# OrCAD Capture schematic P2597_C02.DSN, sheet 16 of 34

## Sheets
16 18_CSI Connector: size Custom
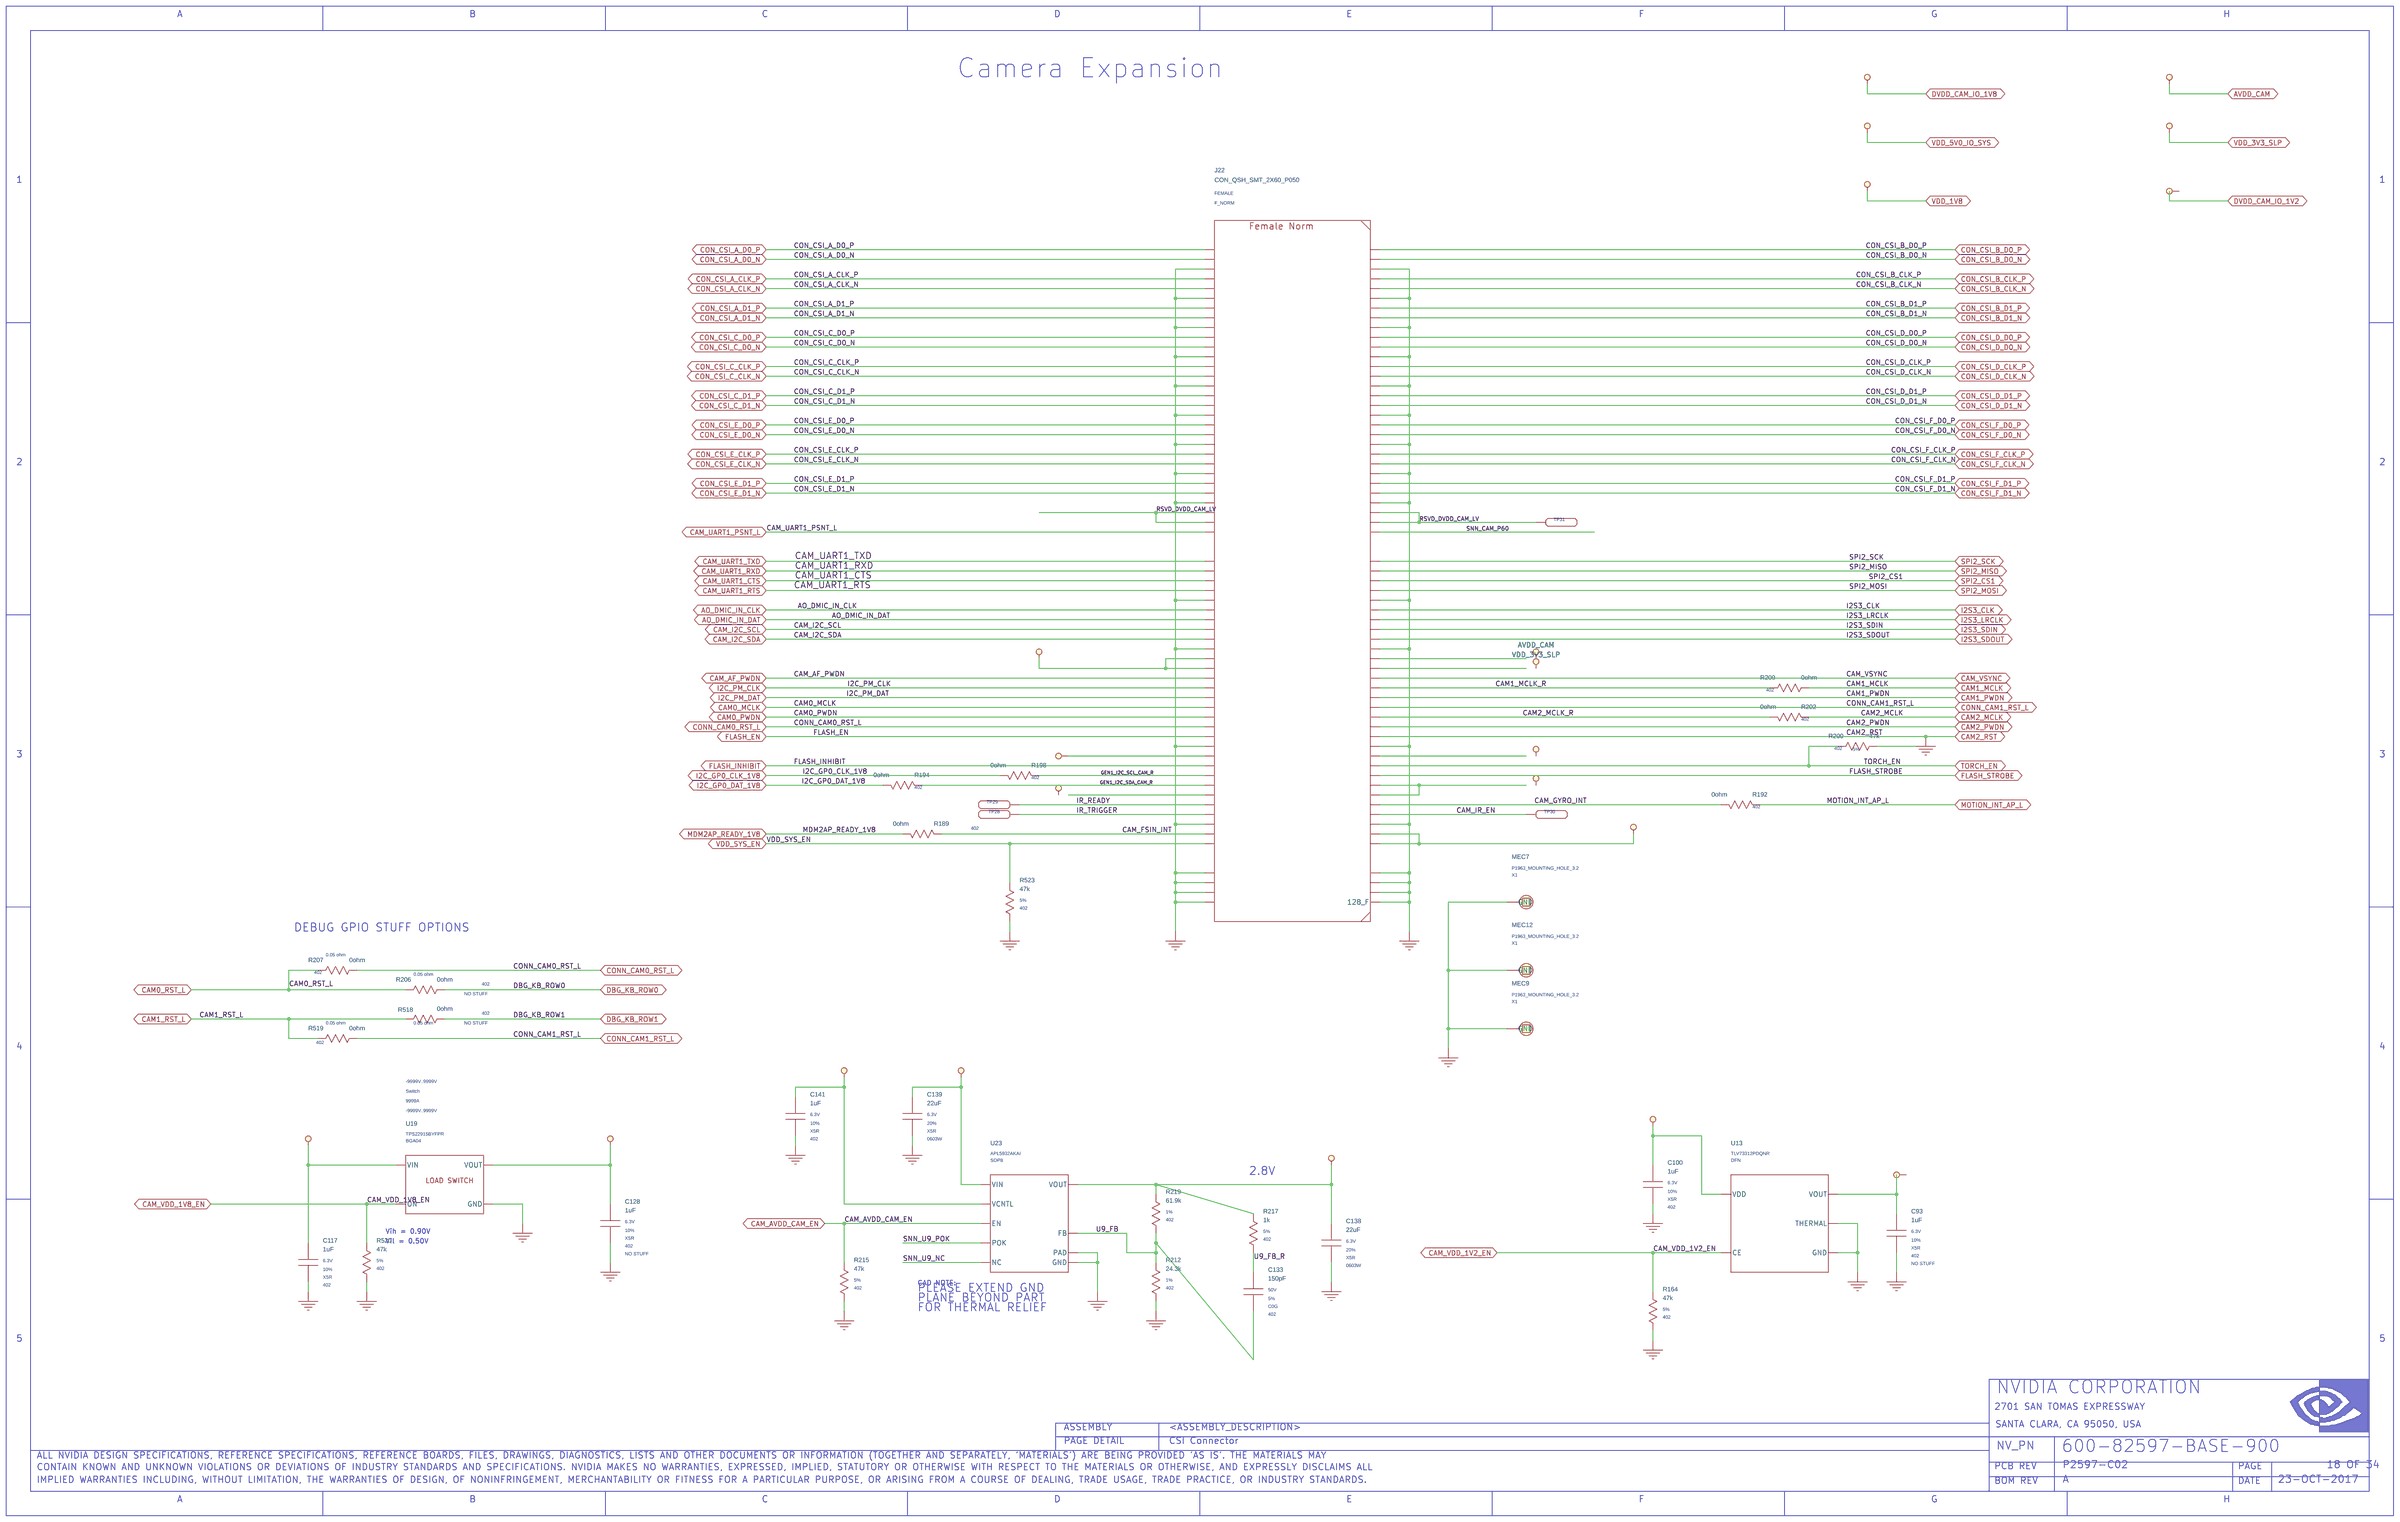
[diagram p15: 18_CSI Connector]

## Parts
C93  1uF  [402]
C100  1uF  [402]
C117  1uF  [402]
C128  1uF  [402]
C133  150pF  [402]
C138  22uF  [0603_LARGE]
C139  22uF  [0603_LARGE]
C141  1uF  [402]
J22  CON_B2B_120  [CON_QSH_120_SMT_ST_P005]
MEC7  MOUNTING_HOLE  [MEC_HOLE_PTH_599C_INT422C_B701C320P]
MEC9  MOUNTING_HOLE  [MEC_HOLE_PTH_599C_INT422C_B701C320P]
MEC12  MOUNTING_HOLE  [MEC_HOLE_PTH_599C_INT422C_B701C320P]
R164  47k  [402]
R189  0ohm  [402]
R192  0ohm  [402]
R194  0ohm  [402]
R198  0ohm  [402]
R200  47k  [402]
R202  0ohm  [402]
R206  0ohm  [402]
R207  0ohm  [402]
R209  0ohm  [402]
R212  24.3k  [402]
R215  47k  [402]
R217  1k  [402]
R219  61.9k  [402]
R518  0ohm  [402]
R519  0ohm  [402]
R520  47k  [402]
R523  47k  [402]
TP28  LABTESTPOINT  [LTPT28C49P]
TP29  LABTESTPOINT  [LTPT28C49P]
TP30  LABTESTPOINT  [LTPT28C49P]
TP31  LABTESTPOINT  [LTPT28C49P]
U13  0mV  [DFN04_P065_010X010_T005X005]
U19  U_SW_LOAD  [BGA_0004_P040_008X008]
U23  [ ]  [SO08_048X038_T030X026]

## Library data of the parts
C93 = C: ASSEMBLY: CAMERA; CDS_LIB: discrete; CDS_PART_NAME: C_0402-1UF,X5R,10%,6.3V,039-0008-000; CDS_PHYS_PART_NAME: C_0402-1UF,X5R,10%,6.3V,039-0008-000-039-0008-000,1UF; CDS_SEC: 1; DEVICE_TYPENAME: C_0402-1UFX5R1063V039-0008-000-039-0008-0001UF; DRAWING: @P2597_C02_LIB.P2597_C02(SCH_1):PAGE18; MAT: X5R; MAX_VOLTAGE: 6.3V; NV_PN: 039-0008-000; PATH: I384; PHYS_PAGE: 18; ROT: 0; SEC: 1; SIGNAL_MODEL: nv_cap; SKU: NO STUFF; TOL: 10%; VER: 1; XY: (-2450,1300)
C100 = C: ASSEMBLY: CAMERA; CDS_LIB: discrete; CDS_PART_NAME: C_0402-1UF,X5R,10%,6.3V,039-0008-000; CDS_PHYS_PART_NAME: C_0402-1UF,X5R,10%,6.3V,039-0008-000-039-0008-000,1UF; CDS_SEC: 1; DEVICE_TYPENAME: C_0402-1UFX5R1063V039-0008-000-039-0008-0001UF; DRAWING: @P2597_C02_LIB.P2597_C02(SCH_1):PAGE18; MAT: X5R; MAX_VOLTAGE: 6.3V; NV_PN: 039-0008-000; PATH: I379; PHYS_PAGE: 18; ROT: 0; SEC: 1; SIGNAL_MODEL: nv_cap; TOL: 10%; VER: 1; XY: (-3700,1550)
C117 = C: ASSEMBLY: CAMERA; CDS_LIB: discrete; CDS_PART_NAME: C_0402-1UF,X5R,10%,6.3V,039-0008-000; CDS_PHYS_PART_NAME: C_0402-1UF,X5R,10%,6.3V,039-0008-000-039-0008-000,1UF; CDS_SEC: 1; DEVICE_TYPENAME: C_0402-1UFX5R1063V039-0008-000-039-0008-0001UF; DRAWING: @P2597_C02_LIB.P2597_C02(SCH_1):PAGE18; MAT: X5R; MAX_VOLTAGE: 6.3V; NV_PN: 039-0008-000; PATH: I175; PHYS_PAGE: 18; ROT: 0; SEC: 1; SIGNAL_MODEL: nv_cap; TOL: 10%; VER: 1; XY: (-10600,1150)
C128 = C: ASSEMBLY: CAMERA; CDS_LIB: discrete; CDS_PART_NAME: C_0402-1UF,X5R,10%,6.3V,039-0008-000; CDS_PHYS_PART_NAME: C_0402-1UF,X5R,10%,6.3V,039-0008-000-039-0008-000,1UF; CDS_SEC: 1; DEVICE_TYPENAME: C_0402-1UFX5R1063V039-0008-000-039-0008-0001UF; DRAWING: @P2597_C02_LIB.P2597_C02(SCH_1):PAGE18; MAT: X5R; MAX_VOLTAGE: 6.3V; NV_PN: 039-0008-000; PATH: I177; PHYS_PAGE: 18; ROT: 0; SEC: 1; SIGNAL_MODEL: nv_cap; SKU: NO STUFF; TOL: 10%; VER: 1; XY: (-9050,1350)
C133 = C: ASSEMBLY: CAMERA; CDS_LIB: discrete; CDS_PART_NAME: C_0402-150PF,C0G,5%,50V,035-0018-000; CDS_PHYS_PART_NAME: C_0402-150PF,C0G,5%,50V,035-0018-000-035-0018-000,150PF; CDS_SEC: 1; DEVICE_TYPENAME: C_0402-150PFC0G550V035-0018-000-035-0018-000150PF; DRAWING: @P2597_C02_LIB.P2597_C02(SCH_1):PAGE18; MAT: C0G; MAX_VOLTAGE: 50V; NV_PN: 035-0018-000; PATH: I454; PHYS_PAGE: 18; ROT: 0; SEC: 1; SIGNAL_MODEL: nv_cap; TOL: 5%; VER: 1; XY: (-5750,1000)
C138 = C: ASSEMBLY: CAMERA; CDS_LIB: discrete; CDS_PART_NAME: C_0603W-22UF,X5R,20%,6.3V,039-0223-000; CDS_PHYS_PART_NAME: C_0603W-22UF,X5R,20%,6.3V,039-0223-000-039-0223-000,22UF; CDS_SEC: 1; DEVICE_TYPENAME: C_0603W-22UFX5R2063V039-0223-000-039-0223-00022UF; DRAWING: @P2597_C02_LIB.P2597_C02(SCH_1):PAGE18; MAT: X5R; MAX_VOLTAGE: 6.3V; NV_PN: 039-0223-000; PACK_TYPE: 0603W; PATH: I196; PHYS_PAGE: 18; ROT: 0; SEC: 1; SEC_TYPE: 0603W; SIGNAL_MODEL: nv_cap; TOL: 20%; VER: 1; XY: (-5350,1250)
C139 = C: ASSEMBLY: CAMERA; CDS_LIB: discrete; CDS_PART_NAME: C_0603W-22UF,X5R,20%,6.3V,039-0223-000; CDS_PHYS_PART_NAME: C_0603W-22UF,X5R,20%,6.3V,039-0223-000-039-0223-000,22UF; CDS_SEC: 1; DEVICE_TYPENAME: C_0603W-22UFX5R2063V039-0223-000-039-0223-00022UF; DRAWING: @P2597_C02_LIB.P2597_C02(SCH_1):PAGE18; MAT: X5R; MAX_VOLTAGE: 6.3V; NV_PN: 039-0223-000; PACK_TYPE: 0603W; PATH: I201; PHYS_PAGE: 18; ROT: 0; SEC: 1; SEC_TYPE: 0603W; SIGNAL_MODEL: nv_cap; TOL: 20%; VER: 1; XY: (-7500,1900)
C141 = C: ASSEMBLY: CAMERA; CDS_LIB: discrete; CDS_PART_NAME: C_0402-1UF,X5R,10%,6.3V,039-0008-000; CDS_PHYS_PART_NAME: C_0402-1UF,X5R,10%,6.3V,039-0008-000-039-0008-000,1UF; CDS_SEC: 1; DEVICE_TYPENAME: C_0402-1UFX5R1063V039-0008-000-039-0008-0001UF; DRAWING: @P2597_C02_LIB.P2597_C02(SCH_1):PAGE18; MAT: X5R; MAX_VOLTAGE: 6.3V; NV_PN: 039-0008-000; PATH: I445; PHYS_PAGE: 18; ROT: 0; SEC: 1; SIGNAL_MODEL: nv_cap; TOL: 10%; VER: 1; XY: (-8100,1900)
J22 = CON_B2B_120: ANGLE: 0; ASSEMBLY: CAMERA; CDS_LIB: electro_mechanic; CDS_PART_NAME: CON_B2B_120_F_NORM-CON_QSH_SMT_2X60_P050,FEMALE,0.5MM,0,YES,YES,NO,NO,NO,NA,NA,080-1346-000; CDS_PHYS_PART_NAME: CON_B2B_120_F_NORM-CON_QSH_SMT_2X60_P050,FEMALE,0.5MM,0,YES,YES,NO,NO,NO,NA,NA,080-1346-000-080-1346-000; CDS_SEC: 1; DEVICE_TYPENAME: CON_B2B_120_F_NORM-CON_QSH_SMT_2X60_P050FEMALE05MM0YESYESNONONONANA080-1346-000-080-1346-000; DRAWING: @P2597_C02_LIB.P2597_C02(SCH_1):PAGE18; EMI_GROUND_TAB: NO; GENDER: FEMALE; LATCHING: NO; MAX_CURRENT: NA; MAX_VOLTAGE: NA; NV_NAME: CON_QSH_SMT_2X60_P050; NV_PN: 080-1346-000; PACK_TYPE: F_NORM; PATH: I442; PHYS_PAGE: 18; PITCH: 0.5MM; REFLOW: YES; ROT: 0; SEC: 1; SEC_TYPE: F_NORM; SHIELDED: NO; SHROUDED: YES; VER: 1; XY: (-5550,4700)
MEC7 = MOUNTING_HOLE: CDS_LIB: mechanic; CDS_PART_NAME: MOUNTING_HOLE_X1-P1963_MOUNTING_HOLE_3.2; CDS_PHYS_PART_NAME: MOUNTING_HOLE_X1-P1963_MOUNTING_HOLE_3.2; CDS_SEC: 1; DEVICE_TYPENAME: MOUNTING_HOLE_X1-P1963_MOUNTING_HOLE_32; DRAWING: @P2597_C02_LIB.P2597_C02(SCH_1):PAGE18; NV_NAME: P1963_MOUNTING_HOLE_3.2; PACK_TYPE: X1; PATH: I237; PHYS_PAGE: 18; ROT: 0; SEC: 1; SEC_TYPE: X1; VER: 1; XY: (-4350,3000)
MEC9 = MOUNTING_HOLE: CDS_LIB: mechanic; CDS_PART_NAME: MOUNTING_HOLE_X1-P1963_MOUNTING_HOLE_3.2; CDS_PHYS_PART_NAME: MOUNTING_HOLE_X1-P1963_MOUNTING_HOLE_3.2; CDS_SEC: 1; DEVICE_TYPENAME: MOUNTING_HOLE_X1-P1963_MOUNTING_HOLE_32; DRAWING: @P2597_C02_LIB.P2597_C02(SCH_1):PAGE18; NV_NAME: P1963_MOUNTING_HOLE_3.2; PACK_TYPE: X1; PATH: I238; PHYS_PAGE: 18; ROT: 0; SEC: 1; SEC_TYPE: X1; VER: 1; XY: (-4350,2350)
MEC12 = MOUNTING_HOLE: CDS_LIB: mechanic; CDS_PART_NAME: MOUNTING_HOLE_X1-P1963_MOUNTING_HOLE_3.2; CDS_PHYS_PART_NAME: MOUNTING_HOLE_X1-P1963_MOUNTING_HOLE_3.2; CDS_SEC: 1; DEVICE_TYPENAME: MOUNTING_HOLE_X1-P1963_MOUNTING_HOLE_32; DRAWING: @P2597_C02_LIB.P2597_C02(SCH_1):PAGE18; NV_NAME: P1963_MOUNTING_HOLE_3.2; PACK_TYPE: X1; PATH: I236; PHYS_PAGE: 18; ROT: 0; SEC: 1; SEC_TYPE: X1; VER: 1; XY: (-4350,2650)
R164 = R#1: ASSEMBLY: CAMERA; CDS_LIB: discrete; CDS_PART_NAME: R_0402-47K,5 %,62.5MW,195-0599-000; CDS_PHYS_PART_NAME: R_0402-47K,5 %,62.5MW,195-0599-000-195-0599-000,47K; CDS_SEC: 1; CHIPS_PART_NAME: R; DEVICE_TYPENAME: R_0402-47K5625MW195-0599-000-195-0599-00047K; DRAWING: @P2597_C02_LIB.P2597_C02(SCH_1):PAGE18; MAX_WATTAGE: 62.5mW; NV_PN: 195-0599-000; PATH: I469; PHYS_PAGE: 18; ROT: 0; SEC: 1; SIGNAL_MODEL: nv_res; TOL: 5%; VER: 2; XY: (-3700,900)
R189 = R: ASSEMBLY: CAMERA; CDS_LIB: discrete; CDS_PART_NAME: R_0402-0OHM,0.05 OHM,62.5MW,195-2655-000; CDS_PHYS_PART_NAME: R_0402-0OHM,0.05 OHM,62.5MW,195-2655-000-0OHM,195-2655-000; CDS_SEC: 1; DEVICE_TYPENAME: R_0402-0OHM005OHM625MW195-2655-000-0OHM195-2655-000; DRAWING: @P2597_C02_LIB.P2597_C02(SCH_1):PAGE18; MAX_WATTAGE: 62.5mW; NV_PN: 195-2655-000; PATH: I441; PHYS_PAGE: 18; ROT: 2; SEC: 1; SIGNAL_MODEL: nv_res; TOL: 0.05 ohm; VER: 1; XY: (-7450,3350)
R192 = R: ASSEMBLY: CAMERA; CDS_LIB: discrete; CDS_PART_NAME: R_0402-0OHM,0.05 OHM,62.5MW,195-2655-000; CDS_PHYS_PART_NAME: R_0402-0OHM,0.05 OHM,62.5MW,195-2655-000-0OHM,195-2655-000; CDS_SEC: 1; DEVICE_TYPENAME: R_0402-0OHM005OHM625MW195-2655-000-0OHM195-2655-000; DRAWING: @P2597_C02_LIB.P2597_C02(SCH_1):PAGE18; MAX_WATTAGE: 62.5mW; NV_PN: 195-2655-000; PATH: I440; PHYS_PAGE: 18; ROT: 2; SEC: 1; SIGNAL_MODEL: nv_res; TOL: 0.05 ohm; VER: 1; XY: (-3250,3500)
R194 = R: ASSEMBLY: CAMERA; CDS_LIB: discrete; CDS_PART_NAME: R_0402-0OHM,0.05 OHM,62.5MW,195-2655-000; CDS_PHYS_PART_NAME: R_0402-0OHM,0.05 OHM,62.5MW,195-2655-000-0OHM,195-2655-000; CDS_SEC: 1; DEVICE_TYPENAME: R_0402-0OHM005OHM625MW195-2655-000-0OHM195-2655-000; DRAWING: @P2597_C02_LIB.P2597_C02(SCH_1):PAGE18; MAX_WATTAGE: 62.5mW; NV_PN: 195-2655-000; PATH: I370; PHYS_PAGE: 18; ROT: 2; SEC: 1; SIGNAL_MODEL: nv_res; TOL: 0.05 ohm; VER: 1; XY: (-7550,3600)
R198 = R: ASSEMBLY: CAMERA; CDS_LIB: discrete; CDS_PART_NAME: R_0402-0OHM,0.05 OHM,62.5MW,195-2655-000; CDS_PHYS_PART_NAME: R_0402-0OHM,0.05 OHM,62.5MW,195-2655-000-0OHM,195-2655-000; CDS_SEC: 1; DEVICE_TYPENAME: R_0402-0OHM005OHM625MW195-2655-000-0OHM195-2655-000; DRAWING: @P2597_C02_LIB.P2597_C02(SCH_1):PAGE18; MAX_WATTAGE: 62.5mW; NV_PN: 195-2655-000; PATH: I373; PHYS_PAGE: 18; ROT: 2; SEC: 1; SIGNAL_MODEL: nv_res; TOL: 0.05 ohm; VER: 1; XY: (-6950,3650)
R200 = R: ASSEMBLY: CAMERA; CDS_LIB: discrete; CDS_PART_NAME: R_0402-47K,5 %,62.5MW,195-0599-000; CDS_PHYS_PART_NAME: R_0402-47K,5 %,62.5MW,195-0599-000-195-0599-000,47K; CDS_SEC: 1; DEVICE_TYPENAME: R_0402-47K5625MW195-0599-000-195-0599-00047K; DRAWING: @P2597_C02_LIB.P2597_C02(SCH_1):PAGE18; MAX_WATTAGE: 62.5mW; NV_PN: 195-0599-000; PATH: I465; PHYS_PAGE: 18; ROT: 0; SEC: 1; SIGNAL_MODEL: nv_res; TOL: 5%; VER: 1; XY: (-2650,3800)
R202 = R: ASSEMBLY: CAMERA; CDS_LIB: discrete; CDS_PART_NAME: R_0402-0OHM,0.05 OHM,62.5MW,195-2655-000; CDS_PHYS_PART_NAME: R_0402-0OHM,0.05 OHM,62.5MW,195-2655-000-0OHM,195-2655-000; CDS_SEC: 1; DEVICE_TYPENAME: R_0402-0OHM005OHM625MW195-2655-000-0OHM195-2655-000; DRAWING: @P2597_C02_LIB.P2597_C02(SCH_1):PAGE18; MAX_WATTAGE: 62.5mW; NV_PN: 195-2655-000; PATH: I169; PHYS_PAGE: 18; ROT: 2; SEC: 1; SIGNAL_MODEL: nv_res; TOL: 0.05 ohm; VER: 1; XY: (-3000,3950)
R206 = R: ASSEMBLY: CAMERA; CDS_LIB: discrete; CDS_PART_NAME: R_0402-0OHM,0.05 OHM,62.5MW,195-2655-000; CDS_PHYS_PART_NAME: R_0402-0OHM,0.05 OHM,62.5MW,195-2655-000-0OHM,195-2655-000; CDS_SEC: 1; DEVICE_TYPENAME: R_0402-0OHM005OHM625MW195-2655-000-0OHM195-2655-000; DRAWING: @P2597_C02_LIB.P2597_C02(SCH_1):PAGE18; MAX_WATTAGE: 62.5mW; NV_PN: 195-2655-000; PATH: I473; PHYS_PAGE: 18; ROT: 0; SEC: 1; SIGNAL_MODEL: nv_res; SKU: NO STUFF; TOL: 0.05 ohm; VER: 1; XY: (-10000,2550)
R207 = R: ASSEMBLY: CAMERA; CDS_LIB: discrete; CDS_PART_NAME: R_0402-0OHM,0.05 OHM,62.5MW,195-2655-000; CDS_PHYS_PART_NAME: R_0402-0OHM,0.05 OHM,62.5MW,195-2655-000-0OHM,195-2655-000; CDS_SEC: 1; DEVICE_TYPENAME: R_0402-0OHM005OHM625MW195-2655-000-0OHM195-2655-000; DRAWING: @P2597_C02_LIB.P2597_C02(SCH_1):PAGE18; MAX_WATTAGE: 62.5mW; NV_PN: 195-2655-000; PATH: I479; PHYS_PAGE: 18; ROT: 0; SEC: 1; SIGNAL_MODEL: nv_res; TOL: 0.05 ohm; VER: 1; XY: (-10450,2650)
R209 = R: ASSEMBLY: CAMERA; CDS_LIB: discrete; CDS_PART_NAME: R_0402-0OHM,0.05 OHM,62.5MW,195-2655-000; CDS_PHYS_PART_NAME: R_0402-0OHM,0.05 OHM,62.5MW,195-2655-000-0OHM,195-2655-000; CDS_SEC: 1; DEVICE_TYPENAME: R_0402-0OHM005OHM625MW195-2655-000-0OHM195-2655-000; DRAWING: @P2597_C02_LIB.P2597_C02(SCH_1):PAGE18; MAX_WATTAGE: 62.5mW; NV_PN: 195-2655-000; PATH: I168; PHYS_PAGE: 18; ROT: 0; SEC: 1; SIGNAL_MODEL: nv_res; TOL: 0.05 ohm; VER: 1; XY: (-3000,4100)
R212 = R#1: ASSEMBLY: CAMERA; CDS_LIB: discrete; CDS_PART_NAME: R_0402-24.3K,1 %,62.5MW,195-0190-000; CDS_PHYS_PART_NAME: R_0402-24.3K,1 %,62.5MW,195-0190-000-195-0190-000,24.3K; CDS_SEC: 1; CHIPS_PART_NAME: R; DEVICE_TYPENAME: R_0402-243K1625MW195-0190-000-195-0190-000243K; DRAWING: @P2597_C02_LIB.P2597_C02(SCH_1):PAGE18; MAX_WATTAGE: 62.5mW; NV_PN: 195-0190-000; PATH: I449; PHYS_PAGE: 18; ROT: 0; SEC: 1; SIGNAL_MODEL: nv_res; TOL: 1%; VER: 2; XY: (-6250,1050)
R215 = R#1: ASSEMBLY: CAMERA; CDS_LIB: discrete; CDS_PART_NAME: R_0402-47K,5 %,62.5MW,195-0599-000; CDS_PHYS_PART_NAME: R_0402-47K,5 %,62.5MW,195-0599-000-195-0599-000,47K; CDS_SEC: 1; CHIPS_PART_NAME: R; DEVICE_TYPENAME: R_0402-47K5625MW195-0599-000-195-0599-00047K; DRAWING: @P2597_C02_LIB.P2597_C02(SCH_1):PAGE18; MAX_WATTAGE: 62.5mW; NV_PN: 195-0599-000; PATH: I452; PHYS_PAGE: 18; ROT: 0; SEC: 1; SIGNAL_MODEL: nv_res; TOL: 5%; VER: 2; XY: (-7850,1050)
R217 = R#1: ASSEMBLY: CAMERA; CDS_LIB: discrete; CDS_PART_NAME: R_0402-1K,5 %,62.5MW,195-0485-000; CDS_PHYS_PART_NAME: R_0402-1K,5 %,62.5MW,195-0485-000-195-0485-000,1K; CDS_SEC: 1; CHIPS_PART_NAME: R; DEVICE_TYPENAME: R_0402-1K5625MW195-0485-000-195-0485-0001K; DRAWING: @P2597_C02_LIB.P2597_C02(SCH_1):PAGE18; MAX_WATTAGE: 62.5mW; NV_PN: 195-0485-000; PATH: I455; PHYS_PAGE: 18; ROT: 0; SEC: 1; SIGNAL_MODEL: nv_res; TOL: 5%; VER: 2; XY: (-5750,1300)
R219 = R#1: ASSEMBLY: CAMERA; CDS_LIB: discrete; CDS_PART_NAME: R_0402-61.9K,1 %,62.5MW,195-0385-000; CDS_PHYS_PART_NAME: R_0402-61.9K,1 %,62.5MW,195-0385-000-195-0385-000,61.9K; CDS_SEC: 1; CHIPS_PART_NAME: R; DEVICE_TYPENAME: R_0402-619K1625MW195-0385-000-195-0385-000619K; DRAWING: @P2597_C02_LIB.P2597_C02(SCH_1):PAGE18; MAX_WATTAGE: 62.5mW; NV_PN: 195-0385-000; PATH: I448; PHYS_PAGE: 18; ROT: 0; SEC: 1; SIGNAL_MODEL: nv_res; TOL: 1%; VER: 2; XY: (-6250,1400)
R518 = R: ASSEMBLY: CAMERA; CDS_LIB: discrete; CDS_PART_NAME: R_0402-0OHM,0.05 OHM,62.5MW,195-2655-000; CDS_PHYS_PART_NAME: R_0402-0OHM,0.05 OHM,62.5MW,195-2655-000-0OHM,195-2655-000; CDS_SEC: 1; DEVICE_TYPENAME: R_0402-0OHM005OHM625MW195-2655-000-0OHM195-2655-000; DRAWING: @P2597_C02_LIB.P2597_C02(SCH_1):PAGE18; MAX_WATTAGE: 62.5mW; NV_PN: 195-2655-000; PATH: I475; PHYS_PAGE: 18; ROT: 0; SEC: 1; SIGNAL_MODEL: nv_res; SKU: NO STUFF; TOL: 0.05 ohm; VER: 1; XY: (-10000,2400)
R519 = R: ASSEMBLY: CAMERA; CDS_LIB: discrete; CDS_PART_NAME: R_0402-0OHM,0.05 OHM,62.5MW,195-2655-000; CDS_PHYS_PART_NAME: R_0402-0OHM,0.05 OHM,62.5MW,195-2655-000-0OHM,195-2655-000; CDS_SEC: 1; DEVICE_TYPENAME: R_0402-0OHM005OHM625MW195-2655-000-0OHM195-2655-000; DRAWING: @P2597_C02_LIB.P2597_C02(SCH_1):PAGE18; MAX_WATTAGE: 62.5mW; NV_PN: 195-2655-000; PATH: I481; PHYS_PAGE: 18; ROT: 0; SEC: 1; SIGNAL_MODEL: nv_res; TOL: 0.05 ohm; VER: 1; XY: (-10450,2300)
R520 = R#1: ASSEMBLY: CAMERA; CDS_LIB: discrete; CDS_PART_NAME: R_0402-47K,5 %,62.5MW,195-0599-000; CDS_PHYS_PART_NAME: R_0402-47K,5 %,62.5MW,195-0599-000-195-0599-000,47K; CDS_SEC: 1; CHIPS_PART_NAME: R; DEVICE_TYPENAME: R_0402-47K5625MW195-0599-000-195-0599-00047K; DRAWING: @P2597_C02_LIB.P2597_C02(SCH_1):PAGE18; MAX_WATTAGE: 62.5mW; NV_PN: 195-0599-000; PATH: I467; PHYS_PAGE: 18; ROT: 0; SEC: 1; SIGNAL_MODEL: nv_res; TOL: 5%; VER: 2; XY: (-10300,1150)
R523 = R#1: ASSEMBLY: CAMERA; CDS_LIB: discrete; CDS_PART_NAME: R_0402-47K,5 %,62.5MW,195-0599-000; CDS_PHYS_PART_NAME: R_0402-47K,5 %,62.5MW,195-0599-000-195-0599-000,47K; CDS_SEC: 1; CHIPS_PART_NAME: R; DEVICE_TYPENAME: R_0402-47K5625MW195-0599-000-195-0599-00047K; DRAWING: @P2597_C02_LIB.P2597_C02(SCH_1):PAGE18; MAX_WATTAGE: 62.5mW; NV_PN: 195-0599-000; PATH: I463; PHYS_PAGE: 18; ROT: 0; SEC: 1; SIGNAL_MODEL: nv_res; TOL: 5%; VER: 2; XY: (-7000,3000)
TP28 = LABTESTPOINT#1: CDS_LIB: electro_mechanic; CDS_PART_NAME: LABTESTPOINT_B28-LABTESTPOINT; CDS_PHYS_PART_NAME: LABTESTPOINT_B28-LABTESTPOINT; CDS_SEC: 1; DEVICE_TYPENAME: LABTESTPOINT_B28-LABTESTPOINT; DRAWING: @P2597_C02_LIB.P2597_C02(SCH_1):PAGE18; PACK_TYPE: B28; PATH: I240; PHYS_PAGE: 18; ROT: 0; SEC: 1; VER: 1; XY: (-7000,3450)
TP29 = LABTESTPOINT: CDS_LIB: electro_mechanic; CDS_PART_NAME: LABTESTPOINT_B28-LABTESTPOINT; CDS_PHYS_PART_NAME: LABTESTPOINT_B28-LABTESTPOINT; CDS_SEC: 1; DEVICE_TYPENAME: LABTESTPOINT_B28-LABTESTPOINT; DRAWING: @P2597_C02_LIB.P2597_C02(SCH_1):PAGE18; PACK_TYPE: B28; PATH: I241; PHYS_PAGE: 18; ROT: 2; SEC: 1; VER: 3; XY: (-7000,3500)
TP30 = LABTESTPOINT#1: CDS_LIB: electro_mechanic; CDS_PART_NAME: LABTESTPOINT_B28-LABTESTPOINT; CDS_PHYS_PART_NAME: LABTESTPOINT_B28-LABTESTPOINT; CDS_SEC: 1; DEVICE_TYPENAME: LABTESTPOINT_B28-LABTESTPOINT; DRAWING: @P2597_C02_LIB.P2597_C02(SCH_1):PAGE18; PACK_TYPE: B28; PATH: I239; PHYS_PAGE: 18; ROT: 2; SEC: 1; VER: 1; XY: (-4300,3450)
TP31 = LABTESTPOINT#1: CDS_LIB: electro_mechanic; CDS_PART_NAME: LABTESTPOINT_B28-LABTESTPOINT; CDS_PHYS_PART_NAME: LABTESTPOINT_B28-LABTESTPOINT; CDS_SEC: 1; DEVICE_TYPENAME: LABTESTPOINT_B28-LABTESTPOINT; DRAWING: @P2597_C02_LIB.P2597_C02(SCH_1):PAGE18; PACK_TYPE: B28; PATH: I460; PHYS_PAGE: 18; ROT: 2; SEC: 1; VER: 1; XY: (-4250,4950)
U13 = U_VREG_RP114X: ASSEMBLY: CAMERA; CDS_LIB: power_supply; CDS_PART_NAME: U_VREG_RP114X_DFN-TLV73312PDQNR,LOW DROP OUT/FIXED,0.45V@0.3A,1.2V..1.2V,1.4%,0MV,5.5V,0.3A,0.4W,315-0934-000; CDS_PHYS_PART_NAME: U_VREG_RP114X_DFN-TLV73312PDQNR,LOW DROP OUT/FIXED,0.45V@0.3A,1.2V..1.2V,1.4%,0MV,5.5V,0.3A,0.4W,315-0934-000-0MV,315-0934-000; CDS_SEC: 1; DEVICE_TYPENAME: U_VREG_RP114X_DFN-TLV73312PDQNRLOWDROPOUTFIXED045V03A12V12V140MV55V03A04W315-0934-000-0MV315-0934-000; DRAWING: @P2597_C02_LIB.P2597_C02(SCH_1):PAGE18; FORWARD_VOLTAGE: 0.45V@0.3A; MAX_CURRENT: 0.3A; MAX_VOLTAGE: 5.5V; MAX_WATTAGE: 0.4W; NV_NAME: TLV73312PDQNR; NV_PN: 315-0934-000; OUTPUT_VOLTAGE: 1.2V..1.2V; PACK_TYPE: DFN; PATH: I462; PHYS_PAGE: 18; ROT: 0; SEC: 1; SEC_TYPE: DFN; TOL: 1.40%; TYPE: Low Drop Out/Fixed; VER: 1; XY: (-3050,1350)
U19 = U_SW_LOAD: ASSEMBLY: CAMERA; CDS_LIB: analog; CDS_PART_NAME: U_SW_LOAD_BGA04-TPS22915BYFPR,-9999V..9999V,-9999V..9999V,9999A,SWITCH,115-1834-000; CDS_PHYS_PART_NAME: U_SW_LOAD_BGA04-TPS22915BYFPR,-9999V..9999V,-9999V..9999V,9999A,SWITCH,115-1834-000-115-1834-000; CDS_SEC: 1; DEVICE_TYPENAME: U_SW_LOAD_BGA04-TPS22915BYFPR-9999V9999V-9999V9999V9999ASWITCH115-1834-000-115-1834-000; DRAWING: @P2597_C02_LIB.P2597_C02(SCH_1):PAGE18; MAX_CURRENT: 9999A; MAX_VOLTAGE: -9999V..9999V; NV_NAME: TPS22915BYFPR; NV_PN: 115-1834-000; OUTPUT_VOLTAGE: -9999V..9999V; PACK_TYPE: BGA04; PATH: I404; PHYS_PAGE: 18; ROT: 0; SEC: 1; SEC_TYPE: BGA04; TYPE: Switch; VER: 3; XY: (-9900,1550)
U23 = U_VREG_APL5910: ASSEMBLY: CAMERA; CDS_LIB: power_supply; CDS_PART_NAME: U_VREG_APL5910_SOP8-APL5932AKAI,ULTRA LOW DROP OUT,0.23V@3A,[ ]..5.5V,1.5%,[ ],6V,3A,2W,315-0808-000; CDS_PHYS_PART_NAME: U_VREG_APL5910_SOP8-APL5932AKAI,ULTRA LOW DROP OUT,0.23V@3A,[ ]..5.5V,1.5%,[ ],6V,3A,2W,315-0808-000-315-0808-000,[ ]; CDS_SEC: 1; DEVICE_TYPENAME: U_VREG_APL5910_SOP8-APL5932AKAIULTRALOWDROPOUT023V3A55V156V3A2W315-0808-000-315-0808-000; DRAWING: @P2597_C02_LIB.P2597_C02(SCH_1):PAGE18; FORWARD_VOLTAGE: 0.23V@3A; MAX_CURRENT: 3A; MAX_VOLTAGE: 6V; MAX_WATTAGE: 2W; NV_NAME: APL5932AKAI; NV_PN: 315-0808-000; OUTPUT_VOLTAGE: [ ]..5.5V; PACK_TYPE: SOP8; PATH: I443; PHYS_PAGE: 18; ROT: 0; SEC: 1; SEC_TYPE: SOP8; TOL: 1.50%; TYPE: Ultra Low Drop Out; VER: 1; XY: (-6900,1350)

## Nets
AVDD_CAM: C138.1 J22.81 J22.82 J22.83 R217.1 R219.1 U23.6(VOUT)
DVDD_CAM_IO_1V2: C93.1 J22.101 U13.1(VOUT)
DVDD_CAM_IO_1V8: C128.1 J22.102 U19.A1(VOUT)
GND: C93.2 C100.2 C117.2 C128.2 C138.2 C139.2 C141.2 J22.5 J22.6 J22.11 J22.12 J22.17 J22.18 J22.23 J22.24 J22.29 J22.30 J22.35 J22.36 J22.41 J22.42 J22.47 J22.48 J22.53 J22.54 J22.69 J22.70 J22.79 J22.80 J22.99 J22.100 J22.115 J22.116 J22.121 J22.122 J22.123 J22.124 J22.125 J22.126 J22.127 J22.128(128_F) MEC7.1(GND) MEC9.1(GND) MEC12.1(GND) R164.2 R200.2 R212.2 R215.2 R520.2 R523.2 U13.2(GND) U13.5(THERMAL) U19.B1(GND) U23.8(GND) U23.9(PAD) ; also on sheet 1 2 3 4 5 6 7 9 10 11 12 13 14 15 17 18 19 20 21 22 23 24 25 26 30
VDD_1V8: C100.1 C117.1 U13.4(VDD) U19.A2(VIN) ; also on sheet 4 5 9 10 12 13 17 18 19 20 22 24 30
VDD_3V3_SLP: C139.1 J22.84 J22.108 J22.110 U23.3(VIN) ; also on sheet 4 5 11 17 20 21 22 25
VDD_5V0_IO_SYS: C141.1 J22.109 J22.118 J22.120 U23.4(VCNTL) ; also on sheet 4 5 6 9 11 12 17 18 20 22 26 30
VDD_SYS_EN: J22.119 R523.1 ; also on sheet 13
AO_DMIC_IN_CLK: J22.71 ; also on sheet 18 30
AO_DMIC_IN_DAT: J22.73 ; also on sheet 18 30
CAM0_MCLK: J22.91 ; also on sheet 29
CAM0_PWDN: J22.93 ; also on sheet 29
CAM0_RST_L: R206.1 R207.1 ; also on sheet 29
CAM1_MCLK: R209.2 ; also on sheet 29
CAM1_MCLK_R: J22.88 R209.1
CAM1_PWDN: J22.90 ; also on sheet 29
CAM1_RST_L: R518.1 R519.1 ; also on sheet 29
CAM2_MCLK: R202.1 ; also on sheet 29
CAM2_MCLK_R: J22.94 R202.2
CAM2_PWDN: J22.96 ; also on sheet 13
CAM2_RST: J22.98 ; also on sheet 13
CAM_AF_PWDN: J22.85 ; also on sheet 13
CAM_AVDD_CAM_EN: R215.1 U23.2(EN) ; also on sheet 13
CAM_FSIN_INT: J22.117 R189.1
CAM_GYRO_INT: J22.112 R192.2
CAM_I2C_SCL: J22.75 ; also on sheet 29
CAM_I2C_SDA: J22.77 ; also on sheet 29
CAM_IR_EN: J22.114 TP30.1
CAM_UART1_CTS: J22.65 ; also on sheet 19
CAM_UART1_PSNT_L: J22.59 ; also on sheet 19
CAM_UART1_RTS: J22.67 ; also on sheet 19
CAM_UART1_RXD: J22.63 ; also on sheet 19
CAM_UART1_TXD: J22.61 ; also on sheet 19
CAM_VDD_1V2_EN: R164.1 U13.3(CE) ; also on sheet 13
CAM_VDD_1V8_EN: R520.1 U19.B2(ON) ; also on sheet 13
CAM_VSYNC: J22.86 ; also on sheet 29
CON_CSI_A_CLK_N: J22.9 ; also on sheet 29
CON_CSI_A_CLK_P: J22.7 ; also on sheet 29
CON_CSI_A_D0_N: J22.3 ; also on sheet 29
CON_CSI_A_D0_P: J22.1 ; also on sheet 29
CON_CSI_A_D1_N: J22.15 ; also on sheet 29
CON_CSI_A_D1_P: J22.13 ; also on sheet 29
CON_CSI_B_CLK_N: J22.10 ; also on sheet 29
CON_CSI_B_CLK_P: J22.8 ; also on sheet 29
CON_CSI_B_D0_N: J22.4 ; also on sheet 29
CON_CSI_B_D0_P: J22.2 ; also on sheet 29
CON_CSI_B_D1_N: J22.16 ; also on sheet 29
CON_CSI_B_D1_P: J22.14 ; also on sheet 29
CON_CSI_C_CLK_N: J22.27 ; also on sheet 29
CON_CSI_C_CLK_P: J22.25 ; also on sheet 29
CON_CSI_C_D0_N: J22.21 ; also on sheet 29
CON_CSI_C_D0_P: J22.19 ; also on sheet 29
CON_CSI_C_D1_N: J22.33 ; also on sheet 29
CON_CSI_C_D1_P: J22.31 ; also on sheet 29
CON_CSI_D_CLK_N: J22.28 ; also on sheet 29
CON_CSI_D_CLK_P: J22.26 ; also on sheet 29
CON_CSI_D_D0_N: J22.22 ; also on sheet 29
CON_CSI_D_D0_P: J22.20 ; also on sheet 29
CON_CSI_D_D1_N: J22.34 ; also on sheet 29
CON_CSI_D_D1_P: J22.32 ; also on sheet 29
CON_CSI_E_CLK_N: J22.45 ; also on sheet 29
CON_CSI_E_CLK_P: J22.43 ; also on sheet 29
CON_CSI_E_D0_N: J22.39 ; also on sheet 29
CON_CSI_E_D0_P: J22.37 ; also on sheet 29
CON_CSI_E_D1_N: J22.51 ; also on sheet 29
CON_CSI_E_D1_P: J22.49 ; also on sheet 29
CON_CSI_F_CLK_N: J22.46 ; also on sheet 29
CON_CSI_F_CLK_P: J22.44 ; also on sheet 29
CON_CSI_F_D0_N: J22.40 ; also on sheet 29
CON_CSI_F_D0_P: J22.38 ; also on sheet 29
CON_CSI_F_D1_N: J22.52 ; also on sheet 29
CON_CSI_F_D1_P: J22.50 ; also on sheet 29
CONN_CAM0_RST_L: J22.95 R207.2
CONN_CAM1_RST_L: J22.92 R519.2
DBG_KB_ROW0: R206.2 ; also on sheet 12
DBG_KB_ROW1: R518.2 ; also on sheet 12
FLASH_EN: J22.97 ; also on sheet 29
FLASH_INHIBIT: J22.103 ; also on sheet 13
FLASH_STROBE: J22.106 ; also on sheet 19 29
GEN1_I2C_SCL_CAM_R: J22.105 R198.1
GEN1_I2C_SDA_CAM_R: J22.107 R194.1
I2C_GP0_CLK_1V8: R198.2 ; also on sheet 12 17 24 30
I2C_GP0_DAT_1V8: R194.2 ; also on sheet 12 17 24 30
I2C_PM_CLK: J22.87 ; also on sheet 10 12 18 30
I2C_PM_DAT: J22.89 ; also on sheet 10 12 18 30
I2S3_CLK: J22.72 ; also on sheet 28
I2S3_LRCLK: J22.74 ; also on sheet 28
I2S3_SDIN: J22.76 ; also on sheet 28
I2S3_SDOUT: J22.78 ; also on sheet 28
IR_READY: J22.111 TP29.1
IR_TRIGGER: J22.113 TP28.1
MDM2AP_READY_1V8: R189.2 ; also on sheet 24 28
MOTION_INT_AP_L: R192.1 ; also on sheet 18 30
RSVD_DVDD_CAM_LV: J22.55 J22.56 J22.57 J22.58 TP31.1
SNN_CAM_P60: J22.60
SNN_U9_NC: U23.5(NC)
SNN_U9_POK: U23.1(POK)
SPI2_CS1: J22.66 ; also on sheet 28
SPI2_MISO: J22.64 ; also on sheet 17 28
SPI2_MOSI: J22.68 ; also on sheet 17 28
SPI2_SCK: J22.62 ; also on sheet 17 28
TORCH_EN: J22.104 R200.1 ; also on sheet 13
U9_FB: C133.2 R212.1 R219.2 U23.7(FB)
U9_FB_R: C133.1 R217.2

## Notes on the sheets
sheet 16
- A
- B
- C
- D
- E
- F
- G
- H
- Camera Expansion
- 1
- 1
- 2
- 2
- 3
- 3
- DEBUG GPIO STUFF OPTIONS
- 4
- 4
- 2.8V
- Vih = 0.90V
- Vil = 0.50V
- CAD NOTE:
- PLEASE EXTEND GND
- PLANE BEYOND PART
- FOR THERMAL RELIEF
- 5
- 5
- NVIDIA CORPORATION
- 2701 SAN TOMAS EXPRESSWAY
- ASSEMBLY
- <ASSEMBLY_DESCRIPTION>
- SANTA CLARA, CA 95050, USA
- PAGE DETAIL
- CSI Connector
- NV_PN
- 600-82597-BASE-900
- ALL NVIDIA DESIGN SPECIFICATIONS, REFERENCE SPECIFICATIONS, REFERENCE BOARDS, FILES, DRAWINGS, DIAGNOSTICS, LISTS AND OTHER DOCUMENTS OR INFORMATION (TOGETHER AND SEPARATELY, 'MATERIALS') ARE BEING PROVIDED 'AS IS'. THE MATERIALS MAY
- CONTAIN KNOWN AND UNKNOWN VIOLATIONS OR DEVIATIONS OF INDUSTRY STANDARDS AND SPECIFICATIONS. NVIDIA MAKES NO WARRANTIES, EXPRESSED, IMPLIED, STATUTORY OR OTHERWISE WITH RESPECT TO THE MATERIALS OR OTHERWISE, AND EXPRESSLY DISCLAIMS ALL
- PCB REV
- P2597-C02
- PAGE
- 18 OF 34
- IMPLIED WARRANTIES INCLUDING, WITHOUT LIMITATION, THE WARRANTIES OF DESIGN, OF NONINFRINGEMENT, MERCHANTABILITY OR FITNESS FOR A PARTICULAR PURPOSE, OR ARISING FROM A COURSE OF DEALING, TRADE USAGE, TRADE PRACTICE, OR INDUSTRY STANDARDS.
- BOM REV
- A
- DATE
- 23-OCT-2017
- A
- B
- C
- D
- E
- F
- G
- H
